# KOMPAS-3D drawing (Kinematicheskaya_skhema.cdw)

Referenced files in D:\ASKON 13\Sys\: Graphic.lcs
Referenced files in D:\Учеба\4 курс\Станки\: Кинематическая схема.cdw
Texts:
  Курсовой проект
  Кинематическая схема токарно-винторезного станка
  125 1 126 1 127 1 128 0 50 1|SPDS|125 1 126 1 127 1 128 0 50 1
  129 1 130 1 131 1 132 0 50 1|SPDS|129 1 130 1 131 1 132 0 50 1
  Symbol type A
  Кинематическая схема коробки скоростей (в общем виде)
  Варианты структурных сеток
  Вариант 2
  Вариант 3
  Вариант 4
  Вариант 5
  Вариант 6
  III
  График частот вращения
  N, кВт
  n,мин -1
  Вариант 1
  (оптимальный)
  Шина, общее изображение ГОСТ 21.614-88
  Стили документа
  Кинематическая схема
  токарно-винторезного
  станка
  Курсовой проект-
  Шереметьев Н
  Давыденко П.А.
  ИМПбд-01-17
Dimensions and other numbers on the sheet: 1:1; 1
